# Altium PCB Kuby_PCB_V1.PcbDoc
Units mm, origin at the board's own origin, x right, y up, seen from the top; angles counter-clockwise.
Board outline 122.6 x 93.98 mm, 2 copper layers (Top Layer, Bottom Layer), stack 1.671 mm thick; 16 components, 29 nets, 97 pads, 0 vias.
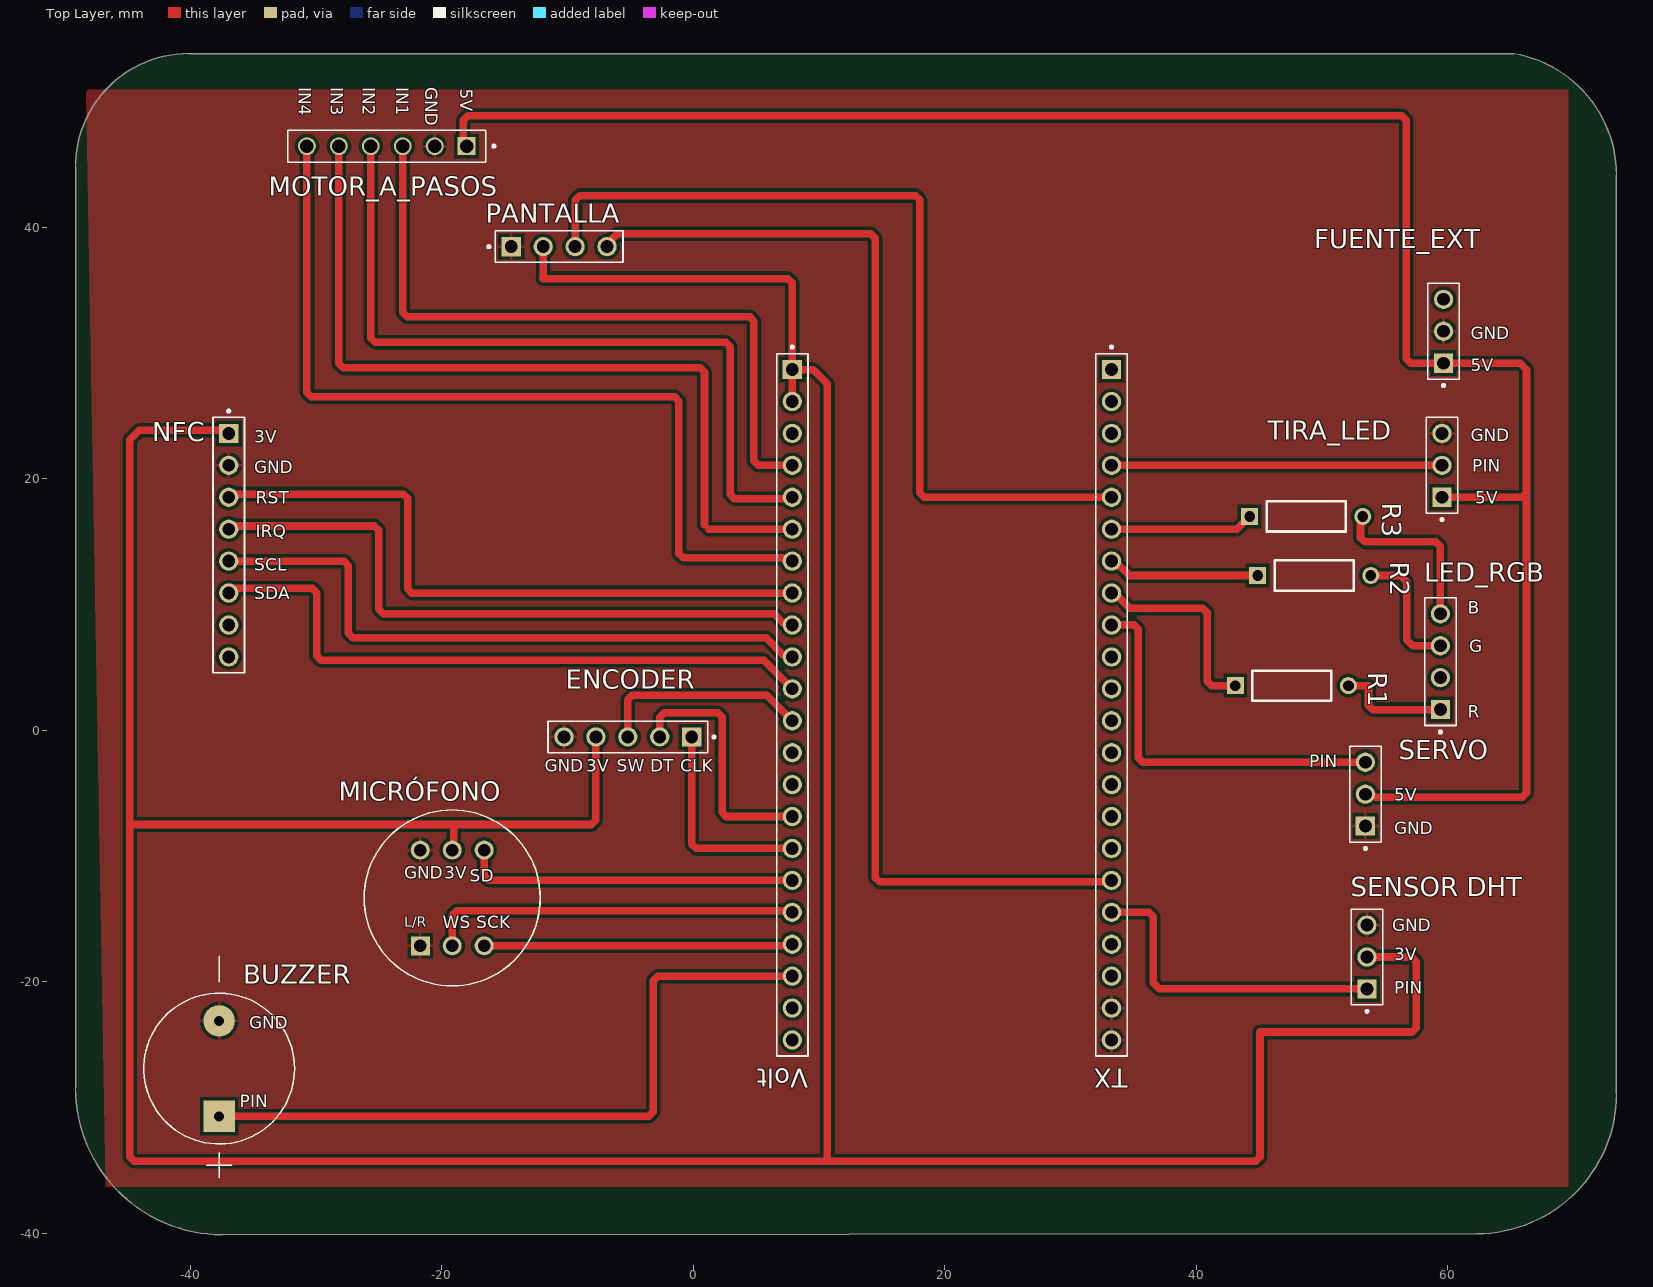
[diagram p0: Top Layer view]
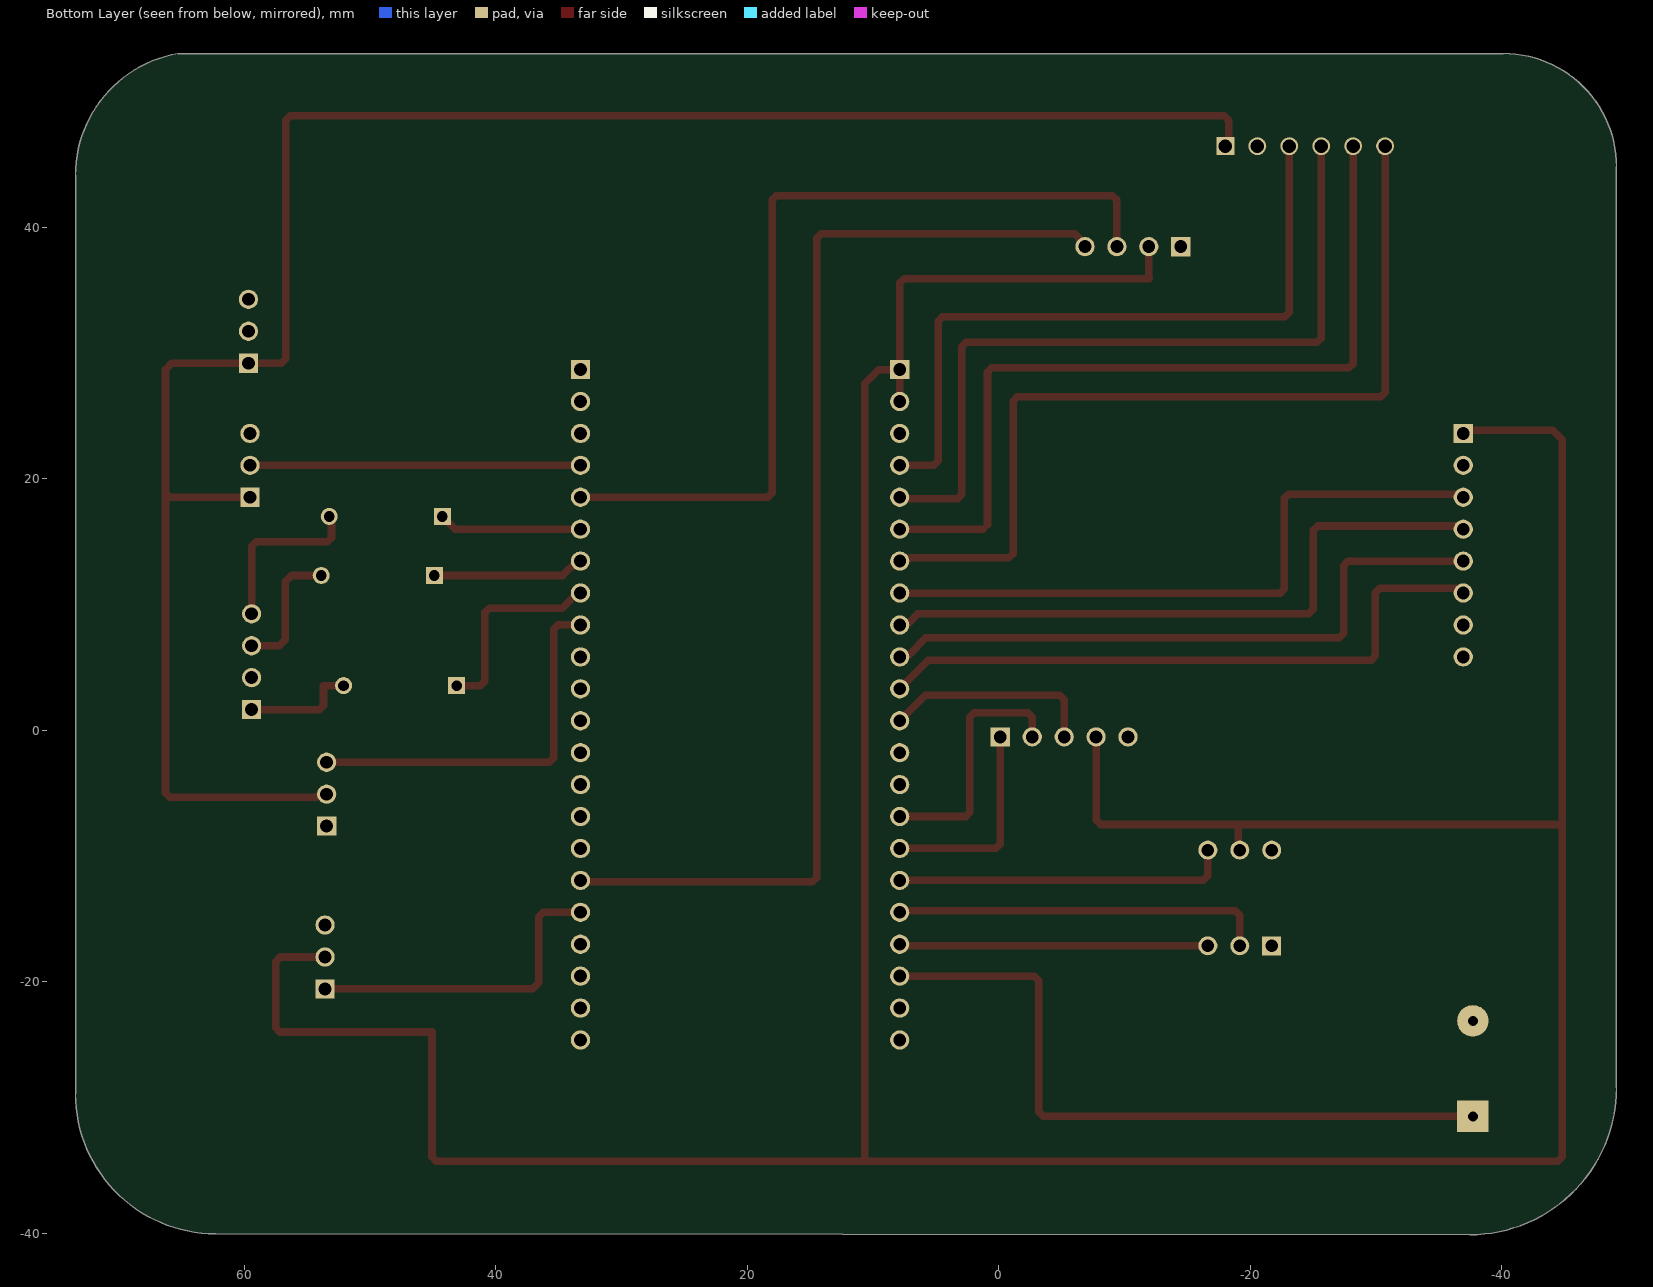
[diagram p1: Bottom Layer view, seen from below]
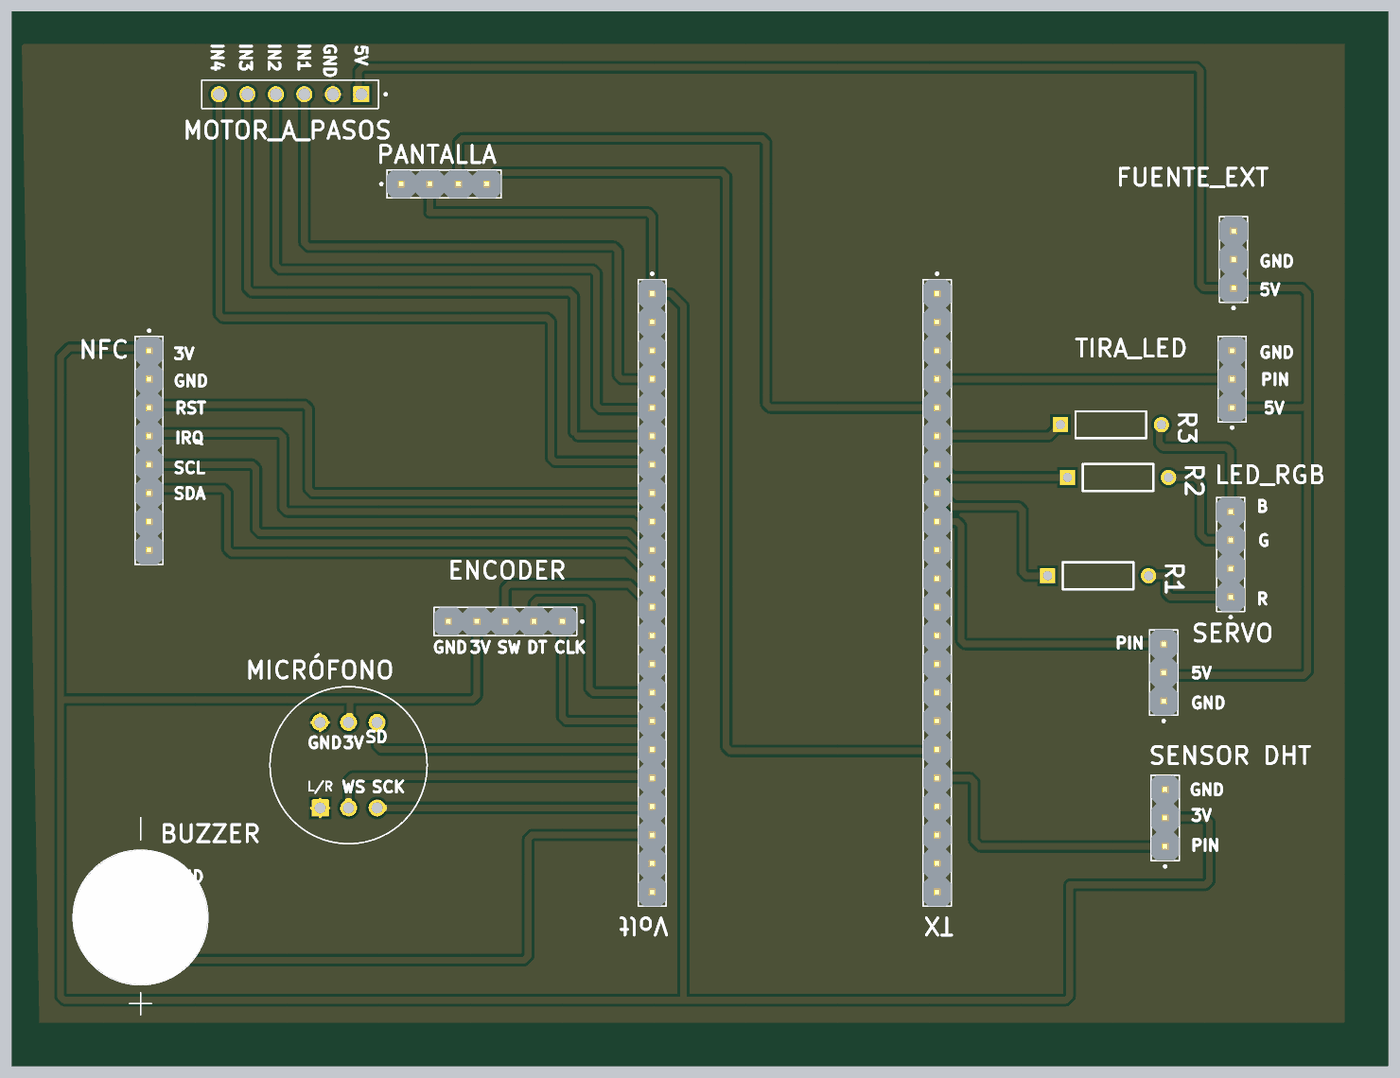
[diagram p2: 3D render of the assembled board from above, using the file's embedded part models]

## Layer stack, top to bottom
Top Solder: solder mask 0.0102, Solder Resist, Dk 3.5
Top Layer: signal copper 0.0356
Dielectric 1: dielectric 1.6, FR-4, Dk 4.8
Bottom Layer: signal copper 0.0356
Bottom Solder: solder mask 0.0102, Solder Resist, Dk 3.5

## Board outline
65.325,53.848 -40.132,53.848 ccw(c-40.132,44.831) -49.149,44.831 -49.149,-28.448 ccw(c-37.468,-28.448) -37.468,-40.129 62.306,-40.06 ccw(c62.298,-28.905) 73.454,-28.905 73.454,44.153 ccw(c63.597,44.144)

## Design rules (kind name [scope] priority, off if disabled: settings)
Clearance [All] p1: gap=0.254 ignorepadtopadclearanceinfootprint=FALSE
PolygonConnect [All] p1: connectstyle=Relief reliefconductorwidth=0.254 reliefentries=4 polygonreliefangle="90 Angle" airgapwidth=0.254
RoutingVias [All] p1: holewidth=0.711 width=1.27 viastyle="Through Hole" minholewidth=0.711 minwidth=1.27 maxholewidth=0.711 maxwidth=1.27
SolderMaskExpansion [All] p1: expansion=0 istentingtop=FALSE
Width [All] p1: maxlimit=3 minlimit=0.254 preferedwidth=0.6 bottomlayer_maxwidth=0.254 bottomlayer_prefwidth=0.254 minimp=50.000000 maximp=50.000000 favimp=50.000000
30 further rules are at their usual default settings.

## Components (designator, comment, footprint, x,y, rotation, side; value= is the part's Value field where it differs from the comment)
BUZZER "MI-1210-5-95T" XDCR_CMI-1210-5-95T -37.719,-26.914 r90 top
ENCODER "DS1021-1X5SF11-B" CONNFLY_DS1021-1X5SF11-B -5.207,-0.521 r180 top
FUENTE_EXT "DS1021-1X3SF11-B" CONNFLY_DS1021-1X3SF11-B 59.695,31.75 r90 top
LED_RGB "DS1021-1X4SF11-B" CONNFLY_DS1021-1X4SF11-B 59.441,5.461 r90 top
MICRÓFONO "OKY3139" MODULE_OKY3139 -19.177,-13.335 r90 top
MOTOR_A_PASOS "B23-1x6-BG1-G" VALCON_B23-1x6-BG1-G -24.384,46.477 r0 top
NFC "DS1021-1X8SF11-N" CONNFLY_DS1021-1X8SF11-N -36.957,14.732 r270 top
PANTALLA "DS1021-1X4SF11-B" CONNFLY_DS1021-1X4SF11-B -10.668,38.481 r0 top
R1 "" RESA60-630X240 47.625,3.556 r0 top
R2 "" RESA60-630X240 49.403,12.319 r0 top
R3 "" RESA60-630X240 48.768,17.018 r0 top
"SENSOR DHT" "DS1021-1X3SF11-B" CONNFLY_DS1021-1X3SF11-B 53.599,-18.034 r90 top
SERVO "DS1021-1X3SF11-B" CONNFLY_DS1021-1X3SF11-B 53.472,-5.08 r90 top
TIRA_LED "DS1021-1X3SF11-B" CONNFLY_DS1021-1X3SF11-B 59.568,21.082 r90 top
TX "DS1021-1X22SF11-B" CONNFLY_DS1021-1X22SF11-B 33.279,2.032 r270 top
Volt "DS1021-1X22SF11-B" CONNFLY_DS1021-1X22SF11-B 7.879,2.032 r270 top

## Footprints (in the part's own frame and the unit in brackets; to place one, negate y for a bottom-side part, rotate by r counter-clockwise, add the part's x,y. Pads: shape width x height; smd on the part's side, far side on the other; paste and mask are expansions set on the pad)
CONNFLY_DS1021-1X3SF11-B [mm]
  rect 1.53x1.53 / inner round 1.53 / far side rect 1.53x1.53 hole 1.02 mask+0.102: 1(-2.54,0)
  round 1.53 hole 1.02 mask+0.102: 2(0,0) 3(2.54,0)
  silkscreen extent -4.42,-1.25 3.81,1.25, body extent -3.81,-1.25 3.81,1.25, height 8.6
CONNFLY_DS1021-1X4SF11-B [mm]
  rect 1.53x1.53 / inner round 1.53 / far side rect 1.53x1.53 hole 1.02 mask+0.102: 1(-3.81,0)
  round 1.53 hole 1.02 mask+0.102: 2(-1.27,0) 3(1.27,0) 4(3.81,0)
  silkscreen extent -5.69,-1.25 5.08,1.25, body extent -5.08,-1.25 5.08,1.25, height 8.6
CONNFLY_DS1021-1X5SF11-B [mm]
  rect 1.53x1.53 / inner round 1.53 / far side rect 1.53x1.53 hole 1.02 mask+0.102: 1(-5.08,0)
  round 1.53 hole 1.02 mask+0.102: 2(-2.54,0) 3(0,0) 4(2.54,0) 5(5.08,0)
  silkscreen extent -6.96,-1.25 6.35,1.25, body extent -6.35,-1.25 6.35,1.25, height 8.6
CONNFLY_DS1021-1X8SF11-N [mm]
  rect 1.53x1.53 / inner round 1.53 / far side rect 1.53x1.53 hole 1.02 mask+0.102: 1(-8.89,0)
  round 1.53 hole 1.02 mask+0.102: 2(-6.35,0) 3(-3.81,0) 4(-1.27,0) 5(1.27,0) 6(3.81,0) 7(6.35,0) 8(8.89,0)
  silkscreen extent -10.77,-1.25 10.16,1.25, body extent -10.16,-1.25 10.16,1.25, height 8.6
CONNFLY_DS1021-1X22SF11-B [mm]
  rect 1.53x1.53 / inner round 1.53 / far side rect 1.53x1.53 hole 1.02 mask+0.102: 1(-26.67,0)
  round 1.53 hole 1.02 mask+0.102: 2(-24.13,0) 3(-21.59,0) 4(-19.05,0) 5(-16.51,0) 6(-13.97,0) 7(-11.43,0) 8(-8.89,0) 9(-6.35,0) 10(-3.81,0) 11(-1.27,0) 12(1.27,0) 13(3.81,0) 14(6.35,0) 15(8.89,0) 16(11.43,0) 17(13.97,0) 18(16.51,0) 19(19.05,0) 20(21.59,0) 21(24.13,0) 22(26.67,0)
  silkscreen extent -28.55,-1.25 27.94,1.25, body extent -27.94,-1.25 27.94,1.25, height 8.6
MODULE_OKY3139 [mm]
  rect 1.508x1.508 / inner round 1.508 / far side rect 1.508x1.508 hole 1 mask+0.102: 1(-3.81,2.54)
  round 1.508 hole 1 mask+0.102: 2(-3.81,0) 3(-3.81,-2.54) 4(3.81,-2.54) 5(3.81,0) 6(3.81,2.54)
  silkscreen extent -7,-7 7,7
RESA60-630X240 [mm] "Axial Resistor, 2-Leads, Dia 2.4mm, Body Length 6.3mm"
  rect 1.35x1.35 hole 0.85: 1(-4.5,0)
  round 1.35 hole 0.85: 2(4.5,0)
  silkscreen extent -3.15,-1.2 3.15,1.2, body extent -3.15,-1.2 3.15,1.2, height 2.4
VALCON_B23-1x6-BG1-G [mm]
  rect 1.42x1.42 hole 1.07: 01(6.35,0)
  round 1.42 hole 1.07: 02(3.81,0) 03(1.27,0) 04(-1.27,0) 05(-3.81,0) 06(-6.35,0)
  silkscreen extent -7.87,-1.27 8.62,1.27
XDCR_CMI-1210-5-95T [mm]
  round 2.5 hole 0.8: N(3.8,0)
  rect 2.5x2.5 / inner round 2.5 / far side rect 2.5x2.5 hole 0.8: P(-3.8,0)
  silkscreen extent -8.69,-6 8.92,6, body extent -6,-6 6,6, height 7

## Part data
BUZZER: library part CMI-1210-5-95T, "12 mm, 5 Vdc, 98 dB, Through Hole, Magnetic Audio Indicator Buzzer", Package=None
ENCODER: "5 position 2.54mm single row vertical pin header through hole", Package=None
FUENTE_EXT "SENSOR DHT" SERVO TIRA_LED: "3 position 2.54mm single row vertical pin header through hole", Package=None
LED_RGB PANTALLA: "4 position 2.54mm single row vertical pin header through hole", Package=None
MICRÓFONO: "Module: audio; microphone; I2S; IC: INMP441; SNR: 61dB; 60HzÃ·15kHz", Package=None
MOTOR_A_PASOS: Package=None
NFC: "8 position 2.54mm single row vertical pin header through hole", Package=None
R1 R2 R3: library part CMP-1659-00071-1, "Axial Resistor, 100 Ohm, +/- 1%, 0.25 W, -55 to 155 degC, 2-Pin THD, RoHS, Bulk", Case\Package=Axial, Max Operating Temperature="155 degC", Min Operating Temperature="-55 degC", Package Quantity=200, Power Rating="250 mW", Resistance="4.75 kohm", Tolerance=1%, Type (Resistor)="Metal Film", Voltage Rating="250 V"
TX Volt: "22 position 2.54mm single row vertical pin header through hole", Manufacturer=Connfly

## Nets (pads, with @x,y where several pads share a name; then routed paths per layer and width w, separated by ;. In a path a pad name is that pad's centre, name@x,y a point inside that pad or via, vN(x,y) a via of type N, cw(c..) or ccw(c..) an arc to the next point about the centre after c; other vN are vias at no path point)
3V3: "SENSOR DHT.2" ENCODER.4 MICRÓFONO.5 NFC.1 PANTALLA.2 Volt.1 Volt.2 | length 329.5
  Top Layer w0.6: NFC.1@-36.957,23.876 -44.069,23.876 -44.844,23.101 -44.844,-7.493 ; -35.319,-34.29 -44.493,-34.29 -44.844,-33.939 -44.844,-7.493 ; -35.306,-34.29 10.673,-34.29 ; -19.05,-8.763 -19.05,-7.493 ; PANTALLA.2 -11.938,35.971 -11.968,35.941 7.528,35.941 7.879,35.59 Volt.1 ; ENCODER.4 -7.747,-7.142 -8.098,-7.493 -19.05,-7.493 ; Volt.2 Volt.1 ; 53.599,-18.034 57.155,-18.034 57.536,-18.415 57.536,-23.652 57.185,-24.003 45.09,-24.003 45.09,-33.939 44.739,-34.29 10.673,-34.29 ; -44.844,-7.493 -19.05,-7.493 ; Volt.1 9.544,28.702 10.673,27.573 10.673,-34.29
5V: FUENTE_EXT.1 MOTOR_A_PASOS.01 SERVO.2 TIRA_LED.1 | length 160
  Top Layer w0.6: MOTOR_A_PASOS.01 -18.288,46.731 -18.288,48.544 -17.937,48.895 56.376,48.895 56.728,48.544 56.728,29.561 57.079,29.21 FUENTE_EXT.1 65.786,29.21 66.294,28.702 66.294,18.893 ; SERVO.2 53.65,-5.258 54.212,-5.258 54.289,-5.334 65.943,-5.334 66.294,-4.983 66.294,18.893 ; TIRA_LED.1 65.943,18.542 66.294,18.893
BUZZER_PIN: BUZZER.P Volt.20 | length 56.3
  Top Layer w0.6: BUZZER.P -3.526,-30.714 -3.175,-30.363 -3.175,-19.909 -2.824,-19.558 Volt.20
DHT_PIN: "SENSOR DHT.1" TX.18 | length 25.9
  Top Layer w0.6: TX.18 36.23,-14.478 36.581,-14.829 36.581,-20.066 37.089,-20.574 53.599,-20.574
ENCODER_CLK: ENCODER.1 Volt.16 | length 16.9
  Top Layer w0.6: ENCODER.1@-0.127,-0.344 -0.127,-9.047 0.224,-9.398 Volt.16
ENCODER_DT: ENCODER.2 Volt.15 | length 20.1
  Top Layer w0.6: ENCODER.2 -2.667,1.046 -2.316,1.397 1.94,1.397 2.291,1.046 2.291,-6.507 2.643,-6.858 Volt.15
ENCODER_SW: ENCODER.3 Volt.12 | length 17
  Top Layer w0.6: ENCODER.3 -5.207,2.443 -4.856,2.794 5.847,2.794 Volt.12
GND: "SENSOR DHT.3" BUZZER.N ENCODER.5 FUENTE_EXT.2 MICRÓFONO.1 MICRÓFONO.6 MOTOR_A_PASOS.02 NFC.2 PANTALLA.1 SERVO.1 TIRA_LED.3 TX.21 TX.22
LED_B: R3.1 TX.6 | length 11.4
  Top Layer w0.6: TX.6 43.252,16.002 R3.1
LED_G: R2.1 TX.7 | length 12.1
  Top Layer w0.6: TX.7 33.531,13.462 34.674,12.319 R2.1
LED_R: R1.1 TX.8 | length 16.1
  Top Layer w0.6: TX.8 33.531,10.922 34.729,9.724 40.543,9.724 40.894,9.373 40.894,3.907 41.245,3.556 R1.1
MIC_SCK: MICRÓFONO.3 Volt.19 | length 24.6
  Top Layer w0.6: MICRÓFONO.3 7.752,-17.145 Volt.19
MIC_SD: MICRÓFONO.4 Volt.17 | length 26.7
  Top Layer w0.6: MICRÓFONO.4 -16.637,-11.587 -16.286,-11.938 Volt.17
MIC_WS: MICRÓFONO.2 Volt.18 | length 29.9
  Top Layer w0.6: MICRÓFONO.2@-19.177,-17.391 -19.177,-14.702 -18.826,-14.351 7.752,-14.351 Volt.18
MOTOR_IN1: MOTOR_A_PASOS.03 Volt.4 | length 55.8
  Top Layer w0.6: MOTOR_A_PASOS.03 -23.114,33.244 -22.763,32.893 4.48,32.893 4.831,32.542 4.831,21.433 5.183,21.082 Volt.4
MOTOR_IN2: MOTOR_A_PASOS.04 Volt.5 | length 61
  Top Layer w0.6: MOTOR_A_PASOS.04 -25.654,31.212 -25.303,30.861 2.575,30.861 2.926,30.51 2.926,18.766 3.278,18.415 7.752,18.415 Volt.5
MOTOR_IN3: MOTOR_A_PASOS.05 Volt.6 | length 65.4
  Top Layer w0.6: MOTOR_A_PASOS.05 -28.194,29.18 -27.843,28.829 0.543,28.829 0.894,28.478 0.894,16.353 ; 1.246,16.002 Volt.6
MOTOR_IN4: MOTOR_A_PASOS.06 Volt.7 | length 71.2
  Top Layer w0.6: MOTOR_A_PASOS.06@-30.734,46.782 -30.734,26.894 -30.383,26.543 -1.489,26.543 -1.138,26.192 -1.138,14.067 -0.786,13.716 7.063,13.716 7.139,13.64 7.701,13.64 Volt.7
NetLED_RGB_1: LED_RGB.1 R1.2 | length 9
  Top Layer w0.6: R1.2 53.721,3.556 53.721,2.002 54.072,1.651 LED_RGB.1
NetLED_RGB_3: LED_RGB.3 R2.2 | length 10.5
  Top Layer w0.6: R2.2 56.261,12.319 56.769,11.811 56.769,7.209 57.247,6.731 LED_RGB.3
NetLED_RGB_4: LED_RGB.4 R3.2 | length 13.6
  Top Layer w0.6: R3.2@53.086,16.862 53.124,16.824 53.124,16.344 53.086,16.306 53.086,15.337 53.437,14.986 59.085,14.986 59.441,14.629 LED_RGB.4
PAN_SCL: PANTALLA.3 TX.5 | length 70.1
  Top Layer w0.6: PANTALLA.3 -9.398,42.194 -9.047,42.545 17.683,42.545 18.034,42.194 18.034,18.893 18.385,18.542 TX.5
PAN_SDA: PANTALLA.4 TX.17 | length 91.9
  Top Layer w0.6: PANTALLA.4 -6.858,38.681 -6.042,39.497 14.127,39.497 14.478,39.146 14.478,-11.714 14.829,-12.065 33.152,-12.065 TX.17
PN532_IRQ: NFC.4 Volt.9 | length 51.9
  Top Layer w0.6: NFC.4 -36.703,16.256 -25.37,16.256 -25.019,15.905 -25.019,9.622 -24.668,9.271 6.428,9.271 7.139,8.56 7.701,8.56 Volt.9
PN532_RST: NFC.3 Volt.8 | length 52.4
  Top Layer w0.6: NFC.3 -36.703,18.796 -23.084,18.796 -22.733,18.445 -22.733,11.273 -22.382,10.922 Volt.8
PN532_SCL: NFC.5 Volt.10 | length 51.3
  Top Layer w0.6: NFC.5@-37.146,13.462 -27.783,13.462 -27.432,13.111 -27.432,7.717 -27.081,7.366 5.793,7.366 7.139,6.02 7.701,6.02 Volt.10
PN532_SDA: NFC.6 Volt.11 | length 51.2
  Top Layer w0.6: NFC.6 -36.576,11.303 -30.323,11.303 -29.972,10.952 -29.972,5.939 -29.621,5.588 5.593,5.588 Volt.11
SERVO_PIN: SERVO.3 TX.9 | length 30.7
  Top Layer w0.6: TX.9 35.047,8.382 35.398,8.031 35.398,-2.189 35.75,-2.54 SERVO.3
TIRA_LED_PIN: TIRA_LED.2 TX.4 | length 26.3
  Top Layer w0.6: TX.4 TIRA_LED.2
pads on no net: FUENTE_EXT.3 LED_RGB.2 NFC.7 NFC.8 TX.1 TX.2 TX.3 TX.10 TX.11 TX.12 TX.13 TX.14 TX.15 TX.16 TX.19 TX.20 Volt.3 Volt.13 Volt.14 Volt.21 Volt.22

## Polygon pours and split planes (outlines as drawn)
GND on Top Layer "NONET_L01_P-001" (solid, remove dead copper, pour order 0): -48.3,50.954 69.596,50.954 69.596,-36.295 -46.74,-36.295

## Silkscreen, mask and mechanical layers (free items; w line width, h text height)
Top Overlay:
  text "IN4" at -31.369,51.181 h1 r270
  text "IN3" at -28.829,51.176 h1 r270
  text "IN2" at -26.289,51.176 h1 r270
  text "IN1" at -23.622,51.176 h1 r270
  text "GND" at -21.336,51.176 h1 r270
  text "5V" at -18.542,51.049 h1 r270
  text "GND" at 61.854,31.115 h1
  text "5V" at 61.854,28.575 h1
  text "GND" at 61.854,22.987 h1
  text "3V" at -34.92,22.86 h1
  text "PIN" at 61.981,20.574 h1
  text "GND" at -34.92,20.447 h1
  text "RST" at -34.793,18.034 h1
  text "5V" at 62.235,18.034 h1
  text "IRQ" at -34.793,15.367 h1
  text "SCL" at -34.92,12.7 h1
  text "SDA" at -34.92,10.414 h1
  text "B" at 61.6,9.271 h1
  text "G" at 61.727,6.223 h1
  text "R" at 61.6,1.016 h1
  text "PIN" at 49.022,-2.921 h1
  text "GND" at -11.811,-3.302 h1
  text "3V" at -8.509,-3.302 h1
  text "SW" at -6.096,-3.302 h1
  text "DT" at -3.429,-3.302 h1
  text "CLK" at -1.016,-3.302 h1
  text "5V" at 55.758,-5.588 h1
  text "GND" at 55.758,-8.255 h1
  text "GND" at -22.987,-11.811 h1
  text "3V" at -19.812,-11.811 h1
  text "SD" at -17.78,-12.065 h1
  text "WS" at -19.939,-15.748 h1
  text "SCK" at -17.272,-15.748 h1
  text "GND" at 55.631,-16.002 h1
  text "3V" at 55.758,-18.288 h1
  text "PIN" at 55.758,-20.955 h1
  text "GND" at -35.306,-23.749 h1
  text "PIN" at -36.068,-29.972 h1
